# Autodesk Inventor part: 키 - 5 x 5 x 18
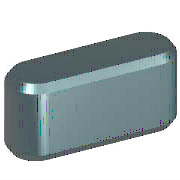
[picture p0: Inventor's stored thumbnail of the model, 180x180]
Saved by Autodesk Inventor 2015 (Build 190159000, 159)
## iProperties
Created: 2012-02
Part Number: 키 - 5 x 5 x 18
Material: 강철, 연강
Description: 키 및 해당 키홈
Document SubType Name: Modeling
Standard: KS B 1311
Designer: mduedu
Standards Organization: KS
Language: ko-KR
Size Designation: 5 x 5 x 18
Categories: <MemberInstance><Categories><Category DisplayName="샤프트 부품" InternalName="7f7aeb1f-a693-4053-b835-cee3144e0d98" Mnemonic="SHFT"><Category DisplayName="키" Interna
Density: 7.86 g/cm^3
Mass: 3.27476 g
Surface Area: 3.57848 cm^2
Volume: 0.416636 cm^3
Appearance: 강철
IsCustomPart: 1
Author: mduedu
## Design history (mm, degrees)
workplane "Work Plane1"
workplane "Work Plane2"
sketch "스케치1"
  geometry: L1 (2.5, 2.5)-(15.5, 2.5); L2 (15.5, -2.5)-(2.5, -2.5); L3 (0, 9.4)-(0, -7.4) reference; L4 (-5, 0)-(30, 0) reference; L5 (18, 0)-(18, 7); A1 r 2.5 centre (2.5, 0) between (2.5, 2.5) and (2.5, -2.5); A2 r 2.5 centre (15.5, 0) between (15.5, -2.5) and (15.5, 2.5)
  constraints: 6 end point, 5 point on circle, 4 tangent, 3 point on line, 2 centre point, 1 horizontal, 1 parallel, 1 perpendicular
  dimensions: "d0" = 2.5 radius of A1 (= 0.5 x PB); "d13" = 2.5 radius of A2 (= 0.5 x PB); "d14" = 18 distance between parallel lines of L5 L3 (= NLG)
extrude "본체1" new body sketch "스케치1" taper "d3" = 0 deg; stored distance "d4" = 10
workplane "Work Plane3"
body "Solid1"
chamfer "모따기1" distance "d8" = 0.4 (= PHH); stored, may be unused: second distance "d9" = 0.4 (= PHH), angle "d15" = 45 deg
other parameters: "d1" = -3 (= -PNT), "d2" = 2 (= PH - PNT), "NLG" = 18 [user parameter; used in 3 equation terms], "PB" = 5 [user parameter; used in 2 equation terms], "PNT" = 3 [user parameter; used in 2 equation terms], "PH" = 5 [user parameter; used in 1 equation term], "PHH" = 0.4 [user parameter; used in 2 equation terms], "d10" = 0, "d16" = 0, "d17" = 0, "d18" = 0, "WDMIN" = 12 [user parameter], "PLB2" = 18 (= NLG) [user parameter], "WDMAX" = 17 [user parameter], "PLB1" = 18 (= NLG) [user parameter], "RR" = 0.16 [user parameter], "PUEB" = 2.3 [user parameter]
